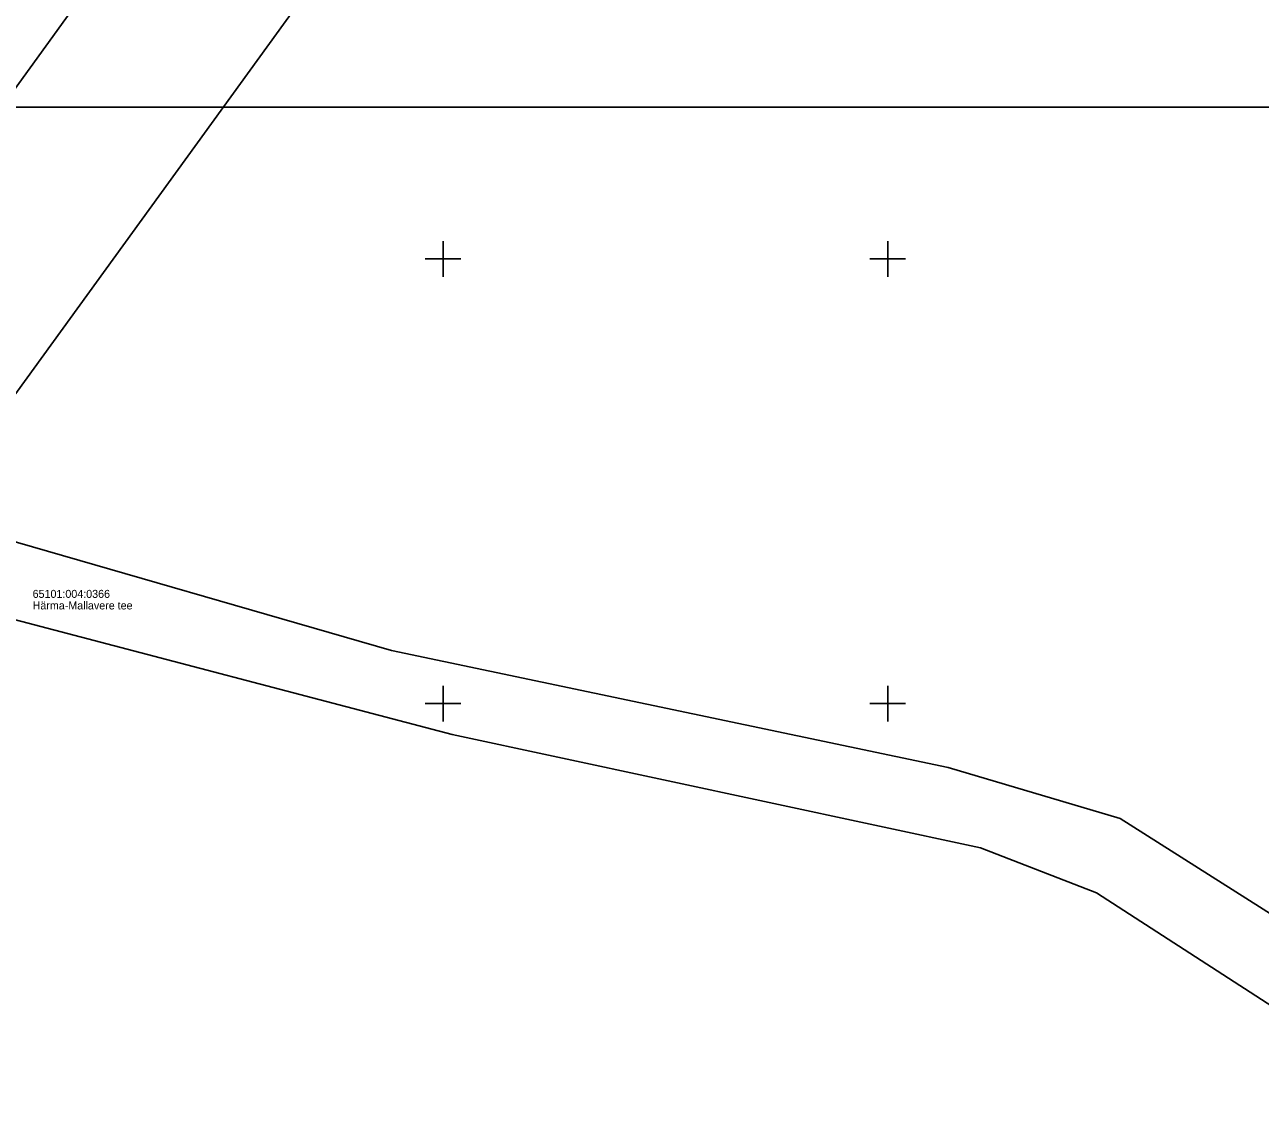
# Model space of a CAD drawing. Extents: x 563121 to 567545, y 6570841 to 6581299.
# Drawn here: x 565852.9 to 565991.9, y 6571804.5 to 6571926.3 of the extents above; entities that cross this region are included whole.
import ezdxf

# ---------------------------------------------------------------- set-up
doc = ezdxf.new("R2010")
doc.units = 0
for name, color, linetype in [('PIIR', 7, 'Continuous'), ('VORK', 7, 'Continuous'), ('VORMISTUS', 7, 'Continuous')]:
    doc.layers.add(name, color=color, linetype=linetype)

msp = doc.modelspace()

# ---------------------------------------------------------------- linework, layer by layer
at = {"layer": 'PIIR'}
for points in [[(566138.88, 6572289.1), (566071.95, 6572189.53), (566056.92, 6572168.48), (566043.44, 6572149.59), (566020.47, 6572117.41), (565845.87, 6571876.56), (565833.02, 6571860.66), (565803.59, 6571818.77), (565766.84, 6571778.8), (565712.27, 6571733.72), (565636.36, 6571689.97), (565561.65, 6571658.97), (565400, 6571600), (565315, 6571572), (565230, 6571552), (564980, 6571552), (564921.56, 6571543.26)], [(564959.63, 6571567.88), (565247.22, 6571575.87), (565310, 6571592), (565385.09, 6571617.94), (565603.34, 6571696.36), (565663.71, 6571724.88), (565720.01, 6571762.52), (565767.05, 6571806.3), (565831.51, 6571891.07), (565894.85, 6571978.6), (565929.68, 6572026.82), (566028.25, 6572163.26), (566043.71, 6572184.75), (566068.58, 6572219.3), (566114.67, 6572283.35)], [(566222.72, 6571643.14), (566175.38, 6571706.88), (566160.83, 6571717.7), (566147.53, 6571725.81), (566110.96, 6571742.32), (566089.86, 6571753.57), (566023.53, 6571796.39), (565973.49, 6571828.72), (565960.44, 6571833.78), (565901.01, 6571846.54), (565851.06, 6571859.65), (565833.02, 6571860.66), (565845.87, 6571876.56), (565848.48, 6571869.16), (565894.21, 6571855.99), (565956.81, 6571842.83), (565976.14, 6571837.09), (566103.84, 6571756.13), (566111.74, 6571748.71), (566152.2, 6571729.75), (566168.46, 6571720.07), (566178.83, 6571711.76), (566186.69, 6571703.16)]]:
    msp.add_lwpolyline(points, dxfattribs=at)
msp.add_lwpolyline([(565833.02, 6571860.66), (565851.06, 6571859.65), (565901.01, 6571846.54), (565960.44, 6571833.78), (565973.49, 6571828.72), (566023.53, 6571796.39), (566089.86, 6571753.57), (566110.96, 6571742.32), (566147.53, 6571725.81), (566160.83, 6571717.7), (565835.49, 6571610.61), (565803.59, 6571818.77)], close=True, dxfattribs=at)
at = {"layer": 'VORK'}
for p, q in [((565900, 6571902), (565900, 6571898)), ((565950, 6571902), (565950, 6571898)), ((565898, 6571900), (565902, 6571900)), ((565948, 6571900), (565952, 6571900)), ((565900, 6571852), (565900, 6571848)), ((565950, 6571852), (565950, 6571848)), ((565898, 6571850), (565902, 6571850)), ((565948, 6571850), (565952, 6571850))]:
    msp.add_line(p, q, dxfattribs=at)
at = {"layer": 'VORMISTUS'}
msp.add_lwpolyline([(565677.6, 6571625.07), (565677.6, 6571917.07), (566085.6, 6571917.07), (566085.6, 6571625.07)], close=True, dxfattribs=at)

# ---------------------------------------------------------------- texts
at = {"layer": 'PIIR'}
for s, p in [('65101:004:0366', (565853.84, 6571861.89)), ('Härma-Mallavere tee', (565853.84, 6571860.59))]:
    msp.add_text(s, height=0.9, dxfattribs=at).set_placement(p)

doc.saveas('drawing.dxf')
